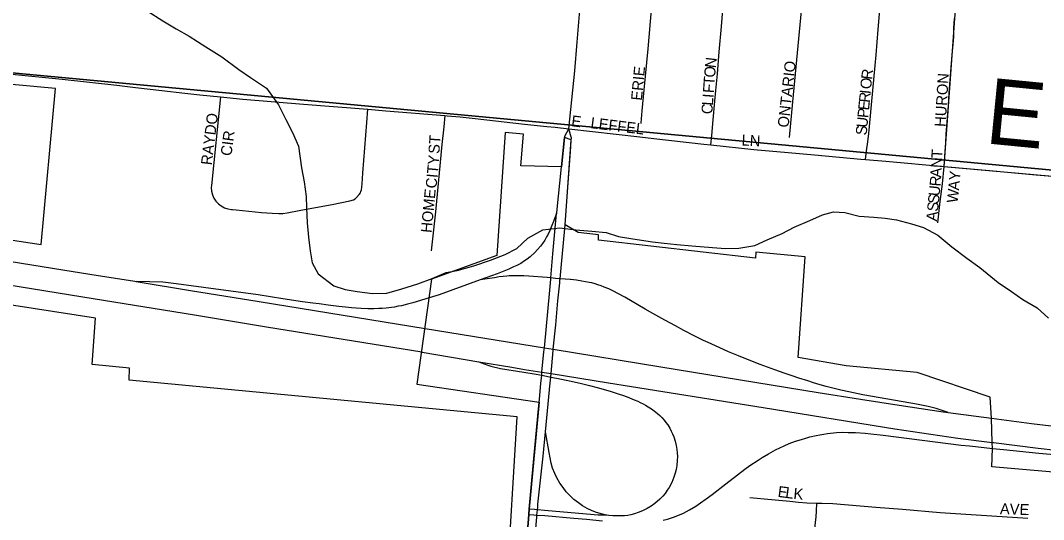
# Model space of a CAD drawing. Extents: x 1410790 to 1770854, y 566777 to 831614.
# Drawn here: x 1598025 to 1602693, y 691023 to 693297 of the extents above; entities that cross this region are included whole.
import ezdxf

# ---------------------------------------------------------------- set-up
doc = ezdxf.new("R2010")
doc.units = 0
for name, color, linetype in [('GM_X_City_Street', 7, 'Continuous'), ('GM_X_City_Street_Text', 7, 'Continuous'), ('GM_X_Corporation', 7, 'Continuous'), ('GM_X_Interchange_Ramps', 7, 'Continuous'), ('GM_X_Interstate_Route', 7, 'Continuous'), ('GM_X_Minor_River', 7, 'Continuous'), ('GM_X_Section', 7, 'Continuous'), ('GM_X_State_Route', 7, 'Continuous'), ('GM_X_Township_Road', 7, 'Continuous'), ('GM_X_Township_Road_Text', 7, 'Continuous'), ('GM_X_Township_Subdivision', 7, 'Continuous'), ('GM_X_Township_Subdivision_Text', 7, 'Continuous')]:
    doc.layers.add(name, color=color, linetype=linetype)

msp = doc.modelspace()

# ---------------------------------------------------------------- linework, layer by layer
at = {"layer": 'GM_X_City_Street'}
for points in [[(1600856.7, 692827.4), (1600857, 692831.3), (1600862.2, 692886), (1600871.2, 692980.7), (1600888.6, 693168.1), (1600904, 693345.1), (1600911.1, 693432.7)], [(1601175.8, 692730.5), (1601179.6, 692772.2), (1601186.1, 692844.6), (1601193.8, 692929.6), (1601198.1, 692977.3), (1601205.1, 693054.7), (1601213, 693155), (1601223.3, 693269.1), (1601234.7, 693404.4)], [(1601534, 692763.3), (1601549.4, 692926.4), (1601567.3, 693118.3), (1601591.3, 693372.9)], [(1601880.6, 692663.8), (1601887.6, 692715.9), (1601889.8, 692732.2), (1601895.5, 692781.3), (1601903.2, 692863.1), (1601907.8, 692912.2), (1601921, 693042.8), (1601929.9, 693141), (1601938.4, 693255.8), (1601946.4, 693345.4)], [(1595780.3, 693288.6), (1595952.1, 693267.6), (1596049.7, 693256.7), (1596228.7, 693236.5), (1596456.6, 693212.3), (1596635.5, 693193), (1596944.7, 693159), (1597237.8, 693127.4), (1597644.9, 693084.2), (1597742.7, 693075.7), (1597970.9, 693054), (1598215.3, 693030.4), (1598464.3, 693001.6), (1598550.5, 692991.9), (1598670.4, 692978.3)], [(1598670.4, 692978.3), (1598775.4, 692966.4)], [(1598775.4, 692966.4), (1598843.7, 692958.7), (1598938.3, 692949.2)], [(1598938.3, 692949.2), (1598896.3, 692544.3), (1598895.9, 692535.8), (1598897.3, 692519.3), (1598901.4, 692503.1), (1598908.1, 692488), (1598917.1, 692474), (1598928.4, 692461.8), (1598941.5, 692451.6), (1598956.1, 692443.7), (1598971.8, 692438.3), (1598988.2, 692435.6), (1598993.2, 692435.3), (1599009.9, 692433.5), (1599124.9, 692422.6), (1599173.8, 692418.7), (1599204.6, 692417.4), (1599223.1, 692418), (1599242.7, 692421), (1599303.9, 692432.5), (1599447.6, 692459.1), (1599527.8, 692474.6), (1599544.4, 692479.8), (1599552.4, 692484.7), (1599559.1, 692489.8), (1599570.8, 692503.8), (1599576.2, 692511.5), (1599578.6, 692518), (1599581, 692525.8), (1599582.8, 692537.1), (1599584, 692553.2), (1599587, 692601.4), (1599606, 692832.5), (1599610.9, 692892.2)], [(1598938.3, 692949.2), (1599039.6, 692939.1), (1599317, 692915.1), (1599610.9, 692892.2)], [(1599610.9, 692892.2), (1599692.9, 692885.7), (1599961.5, 692864.2)], [(1599961.5, 692864.2), (1599956.2, 692812.4), (1599948, 692731.8), (1599918.2, 692425.2), (1599899, 692247.9)], [(1599961.5, 692864.2), (1599971.6, 692863.3), (1600031.3, 692858), (1600100, 692850.7), (1600325.6, 692824.5), (1600426.9, 692814.3), (1600464.6, 692810.5), (1600527.1, 692803.8)], [(1600527.1, 692803.8), (1600851, 692767.2), (1600915.2, 692760), (1601142.9, 692734), (1601175.8, 692730.5)], [(1601175.8, 692730.5), (1601370.7, 692709.3), (1601527.6, 692695.3), (1601647.8, 692684.6), (1601859.7, 692665.7), (1601880.6, 692663.8)], [(1601880.6, 692663.8), (1601973.7, 692655.4), (1602239, 692632.2)], [(1602210.6, 692374.2), (1602221.8, 692471.9), (1602231.7, 692552.9), (1602239, 692632.2)]]:
    msp.add_lwpolyline(points, dxfattribs=at)
at = {"layer": 'GM_X_Corporation'}
for points in [[(1602837.6, 694254.4), (1602630.8, 694268), (1602625.4, 694158.8), (1602366.6, 694182.5), (1602363.7, 694164.4), (1602361.2, 694133.8), (1602356.1, 694072.5), (1602341.1, 693892.6), (1602316.9, 693669.5), (1602287.3, 693305.8), (1602238.9, 692632.2), (1603213.8, 692545.2)], [(1603071.2, 691209.1), (1602457.2, 691262.5), (1602459.6, 691346.7), (1602458.7, 691373.8), (1602455.1, 691484.3), (1602449, 691580.2), (1602117, 691692.2), (1601793.2, 691723.4), (1601573.2, 691760.6), (1601605.6, 692220.6), (1601379.9, 692241.4), (1601378.2, 692213.6), (1600662.9, 692295.2), (1600662.9, 692319.5), (1600570, 692330.8), (1600510.7, 692365.3), (1600538.6, 692752.7), (1600507.6, 692763.4), (1600494.3, 692630.4), (1600308.7, 692634.7), (1600320.2, 692778.4), (1600237.3, 692787), (1600198.5, 692226.2), (1599900.8, 692117.5), (1599833.9, 691639.3), (1600392.2, 691557.9), (1600346.8, 691070.2), (1600344.6, 691046.1), (1600331.7, 690870.5)], [(1600244.6, 690713), (1600292.1, 691491.1), (1598521.2, 691658.2), (1598522.2, 691713), (1598352.7, 691729.8), (1598367.8, 691940.9), (1595414.7, 692397)]]:
    msp.add_lwpolyline(points, dxfattribs=at)
msp.add_lwpolyline([(1597636.9, 693037.6), (1597555.3, 692360.6), (1598119.6, 692275.5), (1598185.5, 692987.3)], close=True, dxfattribs=at)
at = {"layer": 'GM_X_Interchange_Ramps'}
for points in [[(1600471.6, 692417.6), (1600454.1, 692373.8), (1600452.9, 692370.8), (1600446.3, 692354.4), (1600440.5, 692340.4), (1600432.4, 692322.9), (1600426, 692310.8), (1600417.7, 692296.5), (1600407.3, 692281.4), (1600397.3, 692267.8), (1600384.3, 692253), (1600372.8, 692240.3), (1600350.5, 692219.6), (1600337.2, 692209.4), (1600325.5, 692201.1), (1600307.7, 692190.2), (1600289.9, 692181.1), (1600274.9, 692173.6), (1600253.5, 692164.2), (1600223, 692151.6), (1600200.4, 692142.8), (1600122.1, 692114.9), (1599935.7, 692047.3), (1599890.7, 692033.2), (1599814.9, 692009.5), (1599791.8, 692003.5), (1599764, 691997.2), (1599748.9, 691994.5), (1599732.1, 691991.2), (1599717.8, 691989.2), (1599706.1, 691987.7), (1599694.1, 691986.3), (1599676, 691984.9), (1599660.2, 691983.8), (1599638.1, 691982.9), (1599610.8, 691982.9), (1599579.1, 691984.2), (1599556.6, 691985.5), (1599535.8, 691987.3), (1599508.2, 691990), (1599477.3, 691993.8), (1599429.2, 691999.8), (1599388.5, 692005.2), (1599358.7, 692009.2), (1599311.5, 692015.5), (1599222.7, 692028.9), (1599109.6, 692045.9), (1598735.6, 692097.5), (1598674.9, 692103.7), (1598613.5, 692106.5), (1598553.2, 692107.3)], [(1600487.5, 692120.2), (1600466.7, 692121.7), (1600445.3, 692123.5), (1600428.4, 692125), (1600407.3, 692127), (1600366, 692129.9), (1600345, 692131.4), (1600322, 692132.8), (1600297.6, 692133.7), (1600283.4, 692134), (1600268, 692133.8), (1600255.8, 692133), (1600243.7, 692132.1), (1600227, 692130.3), (1600209.3, 692128.1), (1600187.4, 692124.5), (1600155, 692119.7), (1600122.1, 692114.9)], [(1602257.9, 691510.2), (1602229.9, 691520), (1602203.5, 691528.1), (1602166.3, 691537.5), (1602113.3, 691548.4), (1601913, 691582.5), (1601867.9, 691590.9), (1601804.4, 691604.6), (1601767.7, 691612.6), (1601737.6, 691620.1), (1601701.9, 691629.5), (1601674.6, 691637), (1601643.6, 691645.9), (1601617.2, 691653.9), (1601576.3, 691666.6), (1601546, 691677.2), (1601509.1, 691689.2), (1601466.8, 691704.3), (1601400.9, 691728.7), (1601334.6, 691754.9), (1601300.8, 691768.2), (1601255.2, 691787.5), (1601212.8, 691806.3), (1601162.5, 691829.3), (1601141.8, 691839.2), (1601101.9, 691858.5), (1601052.4, 691883.9), (1601013.5, 691904.6), (1600964.8, 691931.5), (1600910.3, 691961.9), (1600875.7, 691981.2), (1600782.6, 692036.2), (1600751.1, 692053.2), (1600730.8, 692063.5), (1600709.5, 692073.5), (1600688.6, 692082.3), (1600674.4, 692087.6), (1600660.3, 692092.5), (1600647.1, 692096.7), (1600632.2, 692100.6), (1600619.5, 692103.4), (1600603, 692106.5), (1600587.3, 692109.1), (1600562, 692113), (1600534.3, 692116.9), (1600533.7, 692117), (1600510.3, 692118.6), (1600487.5, 692120.2)], [(1600117.1, 691741.9), (1600141.6, 691731.9), (1600157.3, 691726), (1600170.9, 691721.8), (1600215.5, 691711.5), (1600321.8, 691693.4), (1600368.8, 691686), (1600403.4, 691679.8), (1600425.6, 691675.8), (1600444.6, 691672), (1600471.5, 691666.7), (1600537.9, 691653.7), (1600585.6, 691642.9), (1600621.3, 691633.6), (1600656.7, 691625), (1600684.4, 691616.9), (1600721.1, 691606), (1600757.5, 691594.2), (1600772.3, 691589), (1600793.3, 691581.4), (1600825.6, 691568.6), (1600841.9, 691561.5), (1600852.8, 691556.3), (1600866, 691549.7), (1600876.4, 691544.2), (1600888.5, 691536.9), (1600904.1, 691527.2), (1600916.5, 691518.2), (1600932.5, 691505.7), (1600942.1, 691496.7), (1600951, 691487.6), (1600961.9, 691475.3), (1600970.5, 691464.3), (1600978.2, 691453.5), (1600987.5, 691438.6), (1600994.4, 691425.8), (1601000.6, 691412.6), (1601005.8, 691399.9), (1601012.6, 691379.5), (1601016.9, 691360.4), (1601020.4, 691341), (1601021.9, 691326), (1601022.9, 691309.2), (1601021.9, 691291), (1601020, 691268.3), (1601016.7, 691251.1), (1601012.8, 691234.3), (1601006.9, 691215.2), (1600997.4, 691191.3), (1600985, 691168.9), (1600976.6, 691156), (1600966.8, 691141.5), (1600956.1, 691128.7), (1600942.1, 691115), (1600920.2, 691094.9), (1600902.5, 691082.8), (1600885.3, 691073), (1600863.4, 691062.3), (1600843.8, 691054.4), (1600826.6, 691048.3), (1600809.9, 691044.1), (1600795.9, 691041.4), (1600781.3, 691039.8), (1600766.5, 691038.8), (1600745.1, 691038.7), (1600728.3, 691039.3), (1600710, 691040.6), (1600693.8, 691043.9), (1600680.8, 691046.9), (1600653.8, 691055.2), (1600634, 691062.6), (1600611.6, 691073.1), (1600590, 691085.1), (1600571, 691098), (1600550, 691114), (1600531.6, 691131.5), (1600515.1, 691148.8), (1600500.7, 691167.7), (1600485.8, 691188.6), (1600473.1, 691212.1), (1600463, 691232.3), (1600453.1, 691257), (1600447, 691279.1), (1600438.1, 691327.6), (1600420.7, 691421.6)], [(1600957.4, 691018.9), (1600976.7, 691024), (1601004.4, 691032.8), (1601024.9, 691040.7), (1601049.7, 691051.8), (1601078.4, 691066.5), (1601106.8, 691083.7), (1601128.7, 691098.2), (1601154, 691116.8), (1601181.6, 691136.3), (1601243.2, 691185.2), (1601297.4, 691226.7), (1601330.9, 691251.5), (1601353.4, 691268), (1601390.9, 691293.3), (1601409.1, 691305.5), (1601438.1, 691322.5), (1601470.1, 691340.3), (1601509, 691358.7), (1601533.3, 691368.7), (1601562.1, 691379.1), (1601588.2, 691387.8), (1601608.2, 691393.9), (1601626.5, 691398.7), (1601655.3, 691405.2), (1601671.8, 691408.3), (1601690.4, 691411.7), (1601708.1, 691414.5), (1601721.7, 691416.1), (1601748.3, 691418.5), (1601776.8, 691420.1), (1601801.8, 691419.7), (1601823, 691419.7), (1601835.8, 691419.4), (1601879.6, 691416.4), (1601905.8, 691413.2), (1601960.8, 691407.1), (1602317.6, 691362), (1602355.5, 691357.8), (1602421.8, 691350.3), (1602459.6, 691346.6), (1602510.7, 691341.2), (1602671.8, 691325.7), (1602831.7, 691312)], [(1600710, 691040.6), (1600682.5, 691041.7), (1600660.8, 691042.8), (1600433, 691061.5), (1600416.9, 691063.2), (1600384, 691066.5), (1600370.5, 691067.8), (1600346.8, 691070.2)], [(1600344.6, 691046.1), (1600368.1, 691044.2), (1600381.8, 691043), (1600418, 691040.1), (1600550, 691028.5), (1600607.3, 691023.9), (1600681.3, 691016.5)]]:
    msp.add_lwpolyline(points, dxfattribs=at)
at = {"layer": 'GM_X_Interstate_Route'}
for points in [[(1595426.6, 692506.2), (1596485.1, 692331.4), (1597248, 692209.8), (1598356.7, 692030.2), (1598819.7, 691955.1), (1599147.3, 691901.2), (1599856.9, 691786.1)], [(1597216.8, 692323), (1598030.7, 692191), (1598266.4, 692152.7), (1598370.6, 692136.8), (1598547.3, 692108.3), (1598553.2, 692107.3), (1598800.5, 692067), (1599114.3, 692015.6), (1599871.7, 691892.5), (1600416.3, 691805.5), (1600456.2, 691799), (1600946.7, 691719.2), (1601665.4, 691601.5), (1601857.9, 691570.9), (1602034.9, 691543.1), (1602234.9, 691513.2), (1602257.9, 691510.2), (1602455.2, 691484.3), (1602637.8, 691460.8), (1602754.4, 691446.7)], [(1599856.9, 691786.1), (1599857.6, 691786), (1600117.1, 691741.9), (1600267, 691716.4), (1600325.6, 691707)], [(1600325.6, 691707), (1600404.8, 691694.3), (1600446, 691687.6), (1600708.4, 691645.4), (1601413.4, 691533.4), (1602014.8, 691436.1), (1602302.3, 691393.9), (1602458.7, 691373.8), (1602465.5, 691373)], [(1602465.5, 691373), (1602668.1, 691347.6), (1602910, 691321), (1603000.9, 691311.6), (1603218.7, 691289.2), (1603490.3, 691266), (1603700.7, 691250.1), (1604147.3, 691224)]]:
    msp.add_lwpolyline(points, dxfattribs=at)
at = {"layer": 'GM_X_Minor_River'}
for points in [[(1598604, 693341.9), (1598675.6, 693295.3), (1598735.2, 693258.8), (1598794.9, 693226.3), (1598870.4, 693177.7), (1598944, 693131), (1599021.5, 693074.4), (1599075.1, 693037.9), (1599148.6, 692989.3), (1599202, 692912.8), (1599235.5, 692846.5), (1599267, 692786.2), (1599294.5, 692723.9), (1599307.7, 692625.7), (1599319.2, 692561.6), (1599328.7, 692495.4), (1599330.3, 692443.4), (1599333.8, 692375.3), (1599339.3, 692309.2), (1599346.8, 692247.1), (1599356.4, 692192.9), (1599384, 692142.7), (1599455.5, 692088.1), (1599507.3, 692071.6), (1599561.1, 692061.2), (1599631, 692052.7)], [(1599631, 692052.7), (1599696.9, 692054.1), (1599764.9, 692073.6), (1599839, 692097.1), (1599903.1, 692120.6), (1599967.2, 692148.1), (1600017.2, 692157.7), (1600093.3, 692179.1), (1600169.4, 692204.6), (1600237.5, 692230), (1600289.6, 692257.7), (1600339.9, 692305.3), (1600408.1, 692342.8), (1600486, 692352.2), (1600559.9, 692343.6), (1600631.7, 692337.1), (1600697.6, 692330.5), (1600753.4, 692312.1), (1600819.2, 692301.5), (1600909, 692288.8), (1600962.9, 692282.4), (1601020.7, 692275.9), (1601088.6, 692269.4), (1601182.4, 692262.7), (1601242.3, 692258.2), (1601302.2, 692259.7), (1601376.2, 692271.2), (1601432.3, 692296.7), (1601500.5, 692326.2), (1601554.6, 692355.8), (1601626.7, 692385.3), (1601684.8, 692410.9), (1601734.9, 692424.5), (1601786.8, 692422.1), (1601852.6, 692405.6), (1601918.4, 692401), (1601970.3, 692396.6), (1602022.2, 692388.2), (1602090, 692369.7), (1602145.8, 692353.2), (1602211.4, 692318.7), (1602274.9, 692266.1), (1602342.5, 692213.6), (1602402.1, 692171), (1602485.4, 692102.3), (1602547, 692061.8), (1602598.7, 692025.4), (1602664.3, 691986.8), (1602715.9, 691940.4)]]:
    msp.add_lwpolyline(points, dxfattribs=at)
at = {"layer": 'GM_X_Section'}
for points in [[(1598351.3, 698519.7), (1603688.3, 697982.3), (1603189.9, 692572.7), (1597838.4, 693072.3)], [(1597838.4, 693072.3), (1603189.9, 692572.7), (1602694.7, 687247), (1597349.3, 687756.6)]]:
    msp.add_lwpolyline(points, close=True, dxfattribs=at)
at = {"layer": 'GM_X_State_Route'}
for points in [[(1600527.1, 692803.8), (1600554.8, 693067.6), (1600565.8, 693198.4), (1600579.7, 693362), (1600585.2, 693425.1), (1600588.4, 693462), (1600613.9, 693754.5), (1600629.9, 693926.9), (1600633.6, 693967), (1600639.5, 694036.8), (1600657.1, 694245.1), (1600681.9, 694523.1), (1600689, 694605.7), (1600726.6, 695046.4), (1600748.9, 695308.3), (1600768.6, 695537.3), (1600772.1, 695577.3), (1600784.6, 695719.7)], [(1600331.7, 690870.5), (1600344.6, 691046.1), (1600344.8, 691048.5), (1600346.8, 691070.2), (1600368, 691300.1), (1600385.9, 691495), (1600392.2, 691557.9), (1600393.6, 691571.5), (1600399.9, 691643), (1600403.4, 691679.8), (1600404.8, 691694.3), (1600413.5, 691786.2), (1600416.3, 691805.5), (1600440.6, 692067.3), (1600444.8, 692118.1), (1600445.3, 692123.5), (1600454.6, 692234.2), (1600471.6, 692417.6), (1600472, 692421.9), (1600494.3, 692630.4), (1600507.6, 692763.3), (1600508.3, 692766.5), (1600509.3, 692769.2), (1600527.1, 692803.8)], [(1600536.2, 692721), (1600538.6, 692752.7), (1600539.1, 692759.6), (1600539, 692762.9), (1600538.4, 692765.8), (1600527.1, 692803.8)], [(1600439.3, 691616), (1600444.6, 691672), (1600446, 691687.6), (1600449.3, 691722.4), (1600455.6, 691792.5), (1600456.2, 691799), (1600467.2, 691910.1), (1600477.8, 692019.9), (1600485.6, 692101.7), (1600486.9, 692114.4), (1600487.5, 692120.2), (1600494.3, 692186.8), (1600501.5, 692266.6), (1600510.7, 692365.3), (1600523.8, 692557.4), (1600536.2, 692721)], [(1600329.3, 690687.7), (1600334.9, 690697.9), (1600339.5, 690708.9), (1600343.8, 690718.9), (1600347.6, 690731.8), (1600356.4, 690796), (1600361.7, 690842.4), (1600370, 690913.5), (1600381, 691033.4), (1600381.8, 691043), (1600384, 691066.5), (1600385.1, 691078), (1600386.4, 691092.5), (1600410.1, 691310.7), (1600420.7, 691421.6), (1600439.1, 691614), (1600439.3, 691616)]]:
    msp.add_lwpolyline(points, dxfattribs=at)
at = {"layer": 'GM_X_Township_Road'}
msp.add_lwpolyline([(1602239, 692632.2), (1602446, 692613.8), (1602659.1, 692594), (1602823, 692579.5), (1603003.3, 692564.2), (1603129.8, 692552.8), (1603173.6, 692548.8), (1603213.9, 692545.2), (1603302.7, 692537.5), (1603449.3, 692527.1), (1603501.5, 692523.7)], dxfattribs=at)
at = {"layer": 'GM_X_Township_Subdivision'}
for points in [[(1602239, 692632.2), (1602243.8, 692700.5), (1602246.7, 692739.9), (1602249.5, 692779.5), (1602254.8, 692853.5), (1602258.8, 692909), (1602262.9, 692966.2), (1602271.3, 693083.6), (1602276.4, 693140.8), (1602280.7, 693189.4), (1602283.2, 693222.7), (1602284.1, 693262.8), (1602287.3, 693305.8)], [(1601352.5, 691122.2), (1601452.4, 691113.5), (1601535.6, 691105.7), (1601575.6, 691102.3), (1601613.6, 691099.1), (1601659.3, 691096.5)], [(1601632.4, 690843), (1601636.8, 690874.5), (1601643.4, 690930.6), (1601655.2, 691035.2), (1601657.2, 691060.5), (1601659.3, 691096.5)], [(1601659.3, 691096.5), (1601670.6, 691096.7), (1601682.3, 691097), (1601731.3, 691095.1), (1601928.6, 691079), (1602050.1, 691069.3), (1602221.2, 691054.5), (1602622.1, 691028)]]:
    msp.add_lwpolyline(points, dxfattribs=at)

# ---------------------------------------------------------------- texts
at = {"layer": 'GM_X_City_Street_Text'}
for s, rotation, p in [('N', 83.7141, (1601197.6, 693078.7)), ('ERIE', 84.4755, (1600860.4, 692930.5)), ('O', 84.6156, (1601193.5, 693035.1)), ('ONTARIO', 83.5584, (1601529.2, 692807.4)), ('R', 83.3058, (1601910.3, 693025.8)), ('T', 85.8978, (1601191, 693000.3)), ('O', 84.4177, (1601906.1, 692982.3)), ('F', 85.9047, (1601188.5, 692965.2)), ('L', 85.9118, (1601184.4, 692908.1)), ('I', 85.8879, (1601186.9, 692943.2)), ('R', 84.4054, (1601900.1, 692921)), ('I', 84.4482, (1601903.9, 692960.4)), ('C', 85.8919, (1601181.5, 692868.6)), ('P', 84.4456, (1601893.2, 692850.9)), ('E', 84.4172, (1601896.6, 692885.9)), ('RAYDO', 83.0227, (1598898, 692635.9)), ('E', 352.8783, (1600536.5, 692815.5)), ('LEFFEL', 353.0183, (1600624.4, 692806.7)), ('U', 84.4177, (1601889, 692807.1)), ('S', 84.4172, (1601885.5, 692772.1)), ('CIR', 82.5728, (1598987.7, 692677.7)), ('ST', 86.4258, (1599936.4, 692688.1)), ('LN', 356.989, (1601314.6, 692727.6)), ('T', 86.8287, (1602230.8, 692668)), ('CITY', 84.6403, (1599923.2, 692530)), ('N', 86.8123, (1602228.3, 692624.1)), ('A', 86.784, (1602225.9, 692580.1)), ('Y', 85.9448, (1602311.3, 692566.2)), ('R', 85.8551, (1602222.9, 692539.7)), ('A', 84.823, (1602307.3, 692521.3)), ('HOME', 84.5582, (1599901.2, 692327.6)), ('U', 84.2538, (1602218.4, 692494.4)), ('W', 83.852, (1602301.1, 692463.5)), ('S', 84.173, (1602211.2, 692424.3)), ('S', 84.1711, (1602214.8, 692459.3)), ('A', 84.1546, (1602206.8, 692380.5))]:
    msp.add_text(s, height=50, rotation=rotation, dxfattribs=at).set_placement(p)
at = {"layer": 'GM_X_Township_Road_Text'}
msp.add_text('E', height=300, rotation=354.4019, dxfattribs=at).set_placement((1602421.1, 692737.9))
at = {"layer": 'GM_X_Township_Subdivision_Text'}
for s, rotation, p in [('HURON', 86.4958, (1602246.3, 692811)), ('E', 352.5191, (1601478.3, 691126.1)), ('L', 352.5295, (1601513.2, 691121.5)), ('K', 355.2802, (1601550.6, 691116.6)), ('AVE', 358.0261, (1602493.6, 691047))]:
    msp.add_text(s, height=50, rotation=rotation, dxfattribs=at).set_placement(p)

doc.saveas('drawing.dxf')
